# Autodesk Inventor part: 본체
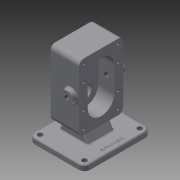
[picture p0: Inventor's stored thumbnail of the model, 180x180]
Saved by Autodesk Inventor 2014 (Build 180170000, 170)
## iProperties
Created: 2020-04
Part Number: 본체
Material: Generic
Document SubType Name: Modeling
Designer: kh
Density: 1 g/cm^3
Appearance: Default
Mass: 544.812 g
Surface Area: 819.925 cm^2
Volume: 544.812 cm^3
Author: kh
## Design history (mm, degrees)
sketch "스케치1"
  geometry: L1 (40, -60)-(-40, -60); L2 (-40, -60)-(-40, 60); L3 (-40, 60)-(40, 60); L4 (40, 60)-(40, -60); L5 (40, -60)-(-40, 60); L6 (-40, -60)-(40, 60); 1 further point
  constraints: 12 end point, 2 midpoint, 2 parallel, 1 horizontal, 1 perpendicular
  dimensions: "d0" = 80 distance of L2.end L3.end; "d1" = 120 distance of L1.end L2.end
extrude "돌출1" new body sketch "스케치1" stored distance "d2" = 53; taper "d3" = 0 deg
node "작업 평면1"
sketch "스케치4"
  geometry: L1 (-60, -40)-(60, -40) reference; L2 (-60, 40)-(-60, -40) reference; L3 (60, 40)-(-60, 40) reference; L4 (0, -48)-(-11, -48); L5 (-11, -48)-(-11, 48); L6 (-11, 48)-(0, 48); L7 (0, 48)-(0, -48); 2 further points
  constraints: 8 end point, 2 parallel, 1 coincident, 1 horizontal, 1 midpoint, 1 perpendicular
  dimensions: "d13" = 60 distance between parallel lines of L7 L2; "d14" = 96 distance between parallel lines of L6 L4; "d15" = 22 diameter of L5 L7
revolve "회전1" sketch "스케치4" stored, may be unused: angle "d16" = 90 deg
node "작업 평면2"
sketch "스케치6"
  geometry: L1 (60, -40)-(60, 40) reference; L2 (-60, -40)-(60, -40) reference; L3 (60, 40)-(-60, 40) reference; C1 r 19 at (22, 0); 1 further point
  constraints: 1 centre point, 1 horizontal alignment
  dimensions: "d20" = 38 diameter of C1; "d21" = 38 distance from line of C1.centre L1
extrude "돌출2" join sketch "스케치6" distance "d22" = 17; taper "d23" = 0 deg
sketch "스케치5"
  geometry: L1 (17, -20)-(-83, -20); L2 (-83, -20)-(-83, 100); L3 (-83, 100)-(17, 100); L4 (17, 100)-(17, -20); L5 (0, 80)-(-53, 80) reference; L6 (-53, 0)-(-53, 80) reference; L7 (-53, 0)-(0, 0) reference; L8 (0, 80)-(0, 0) reference; L9 (17, 21)-(17, 59) reference; 2 further points
  constraints: 8 end point, 2 parallel, 1 collinear, 1 horizontal, 1 horizontal alignment, 1 midpoint, 1 perpendicular
  dimensions: "d18" = 120 distance of L1.end L2.end; "d19" = 100 distance of L1.start L1.end
extrude "돌출3" join sketch "스케치5" distance "d24" = 10; taper "d25" = 0 deg
sketch "스케치7"
  geometry: L1 (-40, -60)-(40, -60) reference; L2 (-60, -80)-(60, -80) reference; L3 (-24, -80)-(24, -80); L4 (24, -80)-(24, -60); L5 (24, -60)-(-24, -60); L6 (-24, -60)-(-24, -80); 2 further points
  constraints: 8 end point, 2 parallel, 2 point on line, 1 horizontal, 1 midpoint, 1 perpendicular, 1 vertical alignment
  dimensions: "d26" = 48 distance of L3.end L3.start
extrude "돌출4" join sketch "스케치7" stored distance "d27" = 1; taper "d28" = 0 deg
sketch "스케치8"
  geometry: L1 (43.5, -80)-(-56.5, -80) reference; L2 (-26.5, -80)-(-16.878, -63.334); L3 (26.5, -80)-(19.552, -67.965); 1 further point
  constraints: 4 end point, 2 point on line
  dimensions: "d31" = 60 deg angle of L1 L2; "d32" = 17 distance of L1.start L3.start; "d33" = 53 distance of L2.start L3.start; "d34" = 60 deg angle of L1 L3
feature "리브1" dims "d35" = 1, "d36" = 48, "d37" = 0, "d38" = 0, "d39" = 1, "d40" = 1
feature "리브2" dims "d41" = 1, "d42" = 48, "d43" = 0, "d44" = 0, "d45" = 1, "d46" = 1
sketch "스케치9"
  geometry: L1 (60, -40)-(60, 40) reference; L2 (60, 40)-(-60, 40) reference; L3 (-60, 40)-(-60, -40) reference; L4 (-60, -40)-(60, -40) reference; L5 (-22, 0)-(22, 0); L6 (-22, 24)-(22, 24); L7 (22, -24)-(-22, -24); A1 r 24 centre (-22, 0) between (-22, 24) and (-22, -24); A2 r 24 centre (22, 0) between (22, -24) and (22, 24); 2 further points
  constraints: 8 end point, 4 point on circle, 4 tangent, 2 centre point, 2 parallel, 1 coincident, 1 midpoint
  dimensions: "d47" = 24 radius of A1; "d48" = 44 distance of L6.start L6.end
extrude "돌출5" cut sketch "스케치9" distance "d49" = 29; taper "d50" = 0 deg
sketch "스케치10"
  geometry: C1 r 12.5 at (-22, 0); C2 r 12.5 at (22, 0); A1 r 24 centre (-22, 0) between (-22, 24) and (-22, -24) reference; A2 r 24 centre (22, 0) between (22, -24) and (22, 24) reference; 1 further point
  constraints: 2 centre point, 2 coincident
  dimensions: "d51" = 25 diameter of C1; "d52" = 25 diameter of C2
extrude "돌출6" cut sketch "스케치10" distance "d53" = 15; taper "d54" = 0 deg
sketch "스케치11"
  geometry: C1 r 12.5 at (0, 0) reference; C2 r 8.5 at (0, 0); 1 further point
  constraints: 1 centre point, 1 coincident
  dimensions: "d55" = 17 diameter of C2
extrude "돌출7" cut sketch "스케치11" stored distance "d56" = 15; taper "d57" = 0 deg
sketch "스케치12"
  geometry: C1 r 8.5 at (0, 0) reference; C2 r 14 at (0, 0); 1 further point
  constraints: 1 centre point, 1 coincident
  dimensions: "d58" = 28 diameter of C2
extrude "돌출8" cut sketch "스케치12" distance "d59" = 7.3; taper "d60" = 0 deg
fillet "모깎기1" dims "d61" = 0.5
chamfer "모따기1" distance "d62" = 0.7; stored, may be unused: second distance "d63" = 2, angle "d64" = 30 deg
chamfer "모따기2" distance "d65" = 1; stored, may be unused: second distance "d66" = 2, angle "d67" = 30 deg
fillet "모깎기2" dims "d68" = 10
fillet "모깎기3" dims "d69" = 9
sketch "스케치13"
  geometry: A1 r 10 centre (-7, 90) between (-7, 100) and (-17, 90) reference; A2 r 10 centre (73, 90) between (83, 90) and (73, 100) reference; A3 r 10 centre (73, -10) between (73, -20) and (83, -10) reference; A4 r 10 centre (-7, -10) between (-17, -10) and (-7, -20) reference; 1 further point
hole "구멍1" sketch "스케치13" at (73, -10), (73, 90), (-7, 90), (-7, -10) diameter "d70" = 9; stored, may be unused: countersink angle "d74" = 90 deg, drill point angle "d76" = 118 deg; dims "d71" = 6, "d72" = 4, "d73" = 2, "d75" = 8
sketch "스케치14"
  geometry: L1 (60, -31)-(60, 31) reference; L2 (51, 40)-(-51, 40) reference; L3 (-60, 31)-(-60, -31) reference; L4 (-51, -40)-(51, -40) reference; L5 (-22, 24)-(22, 24) reference; L6 (22, -24)-(-22, -24) reference; A1 r 9 centre (51, -31) between (51, -40) and (60, -31) reference; A2 r 9 centre (51, 31) between (60, 31) and (51, 40) reference; A3 r 9 centre (-51, 31) between (-51, 40) and (-60, 31) reference; A4 r 9 centre (-51, -31) between (-60, -31) and (-51, -40) reference; A5 r 24 centre (-22, 0) between (-22, 24) and (-22, -24) reference; A6 r 24 centre (22, 0) between (22, -24) and (22, 24) reference; 5 further points
  constraints: 4 horizontal alignment
  dimensions: "d77" = 29 distance of point (-22, -31) A4.centre; "d78" = 44 distance of point (22, -31) point (-22, -31); "d79" = 29 distance of point (-22, 31) A3.centre; "d80" = 44 distance of point (22, 31) point (-22, 31)
hole "구멍2" sketch "스케치14" at (-22, -31), (22, -31), (-22, 31), (22, 31), (-51, -31), (-51, 31), (51, 31), (51, -31) diameter "d81" = 4.459; stored, may be unused: countersink angle "d85" = 90 deg, drill point angle "d87" = 118 deg; dims "d82" = 10, "d83" = 4, "d84" = 2, "d86" = 12
hole "구멍3" diameter "d90" = 8.917; stored, may be unused: countersink angle "d94" = 90 deg, drill point angle "d96" = 118 deg; dims "d88" = 10, "d89" = 10, "d91" = 10, "d92" = 4, "d93" = 2, "d95" = 12
fillet "모깎기4" dims "d97" = 3
fillet "모깎기5" dims "d98" = 3
sketch "스케치15"
  geometry: L1 (66.716, 9.088)-(66.716, 70.912); L2 (66.716, 70.912)-(79.284, 70.912); L3 (79.284, 70.912)-(79.284, 9.088); L4 (79.284, 9.088)-(66.716, 9.088); L5 (-7, -20)-(73, -20) reference; L6 (83, -10)-(83, 90) reference; L7 (66.716, 9.088)-(79.284, 70.912); L8 (66.716, 70.912)-(79.284, 9.088); 2 further points
  constraints: 4 end point, 1 midpoint, 2 other
  dimensions: "d99" = 60 distance from line of L5 point (73, 40); "d100" = 10 distance from line of L6 point (73, 40)
feature "엠보싱1" sketch "스케치15" dims "d0" = 80, "d1" = 120, "d101" = 0.5, "d102" = 0
node "솔리드1"
node "투영된 루프1"
node "투영된 루프2"
node "투영된 루프3"
other parameters: "d12" = -14
